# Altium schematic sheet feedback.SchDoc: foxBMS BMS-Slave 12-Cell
size A3; DocumentNumber: 6; SheetNumber: 6; SheetTotal: 15; AUTHOR: Fraunhofer IISB foxBMS Team; SheetDescription: Passive Balancing Feedback
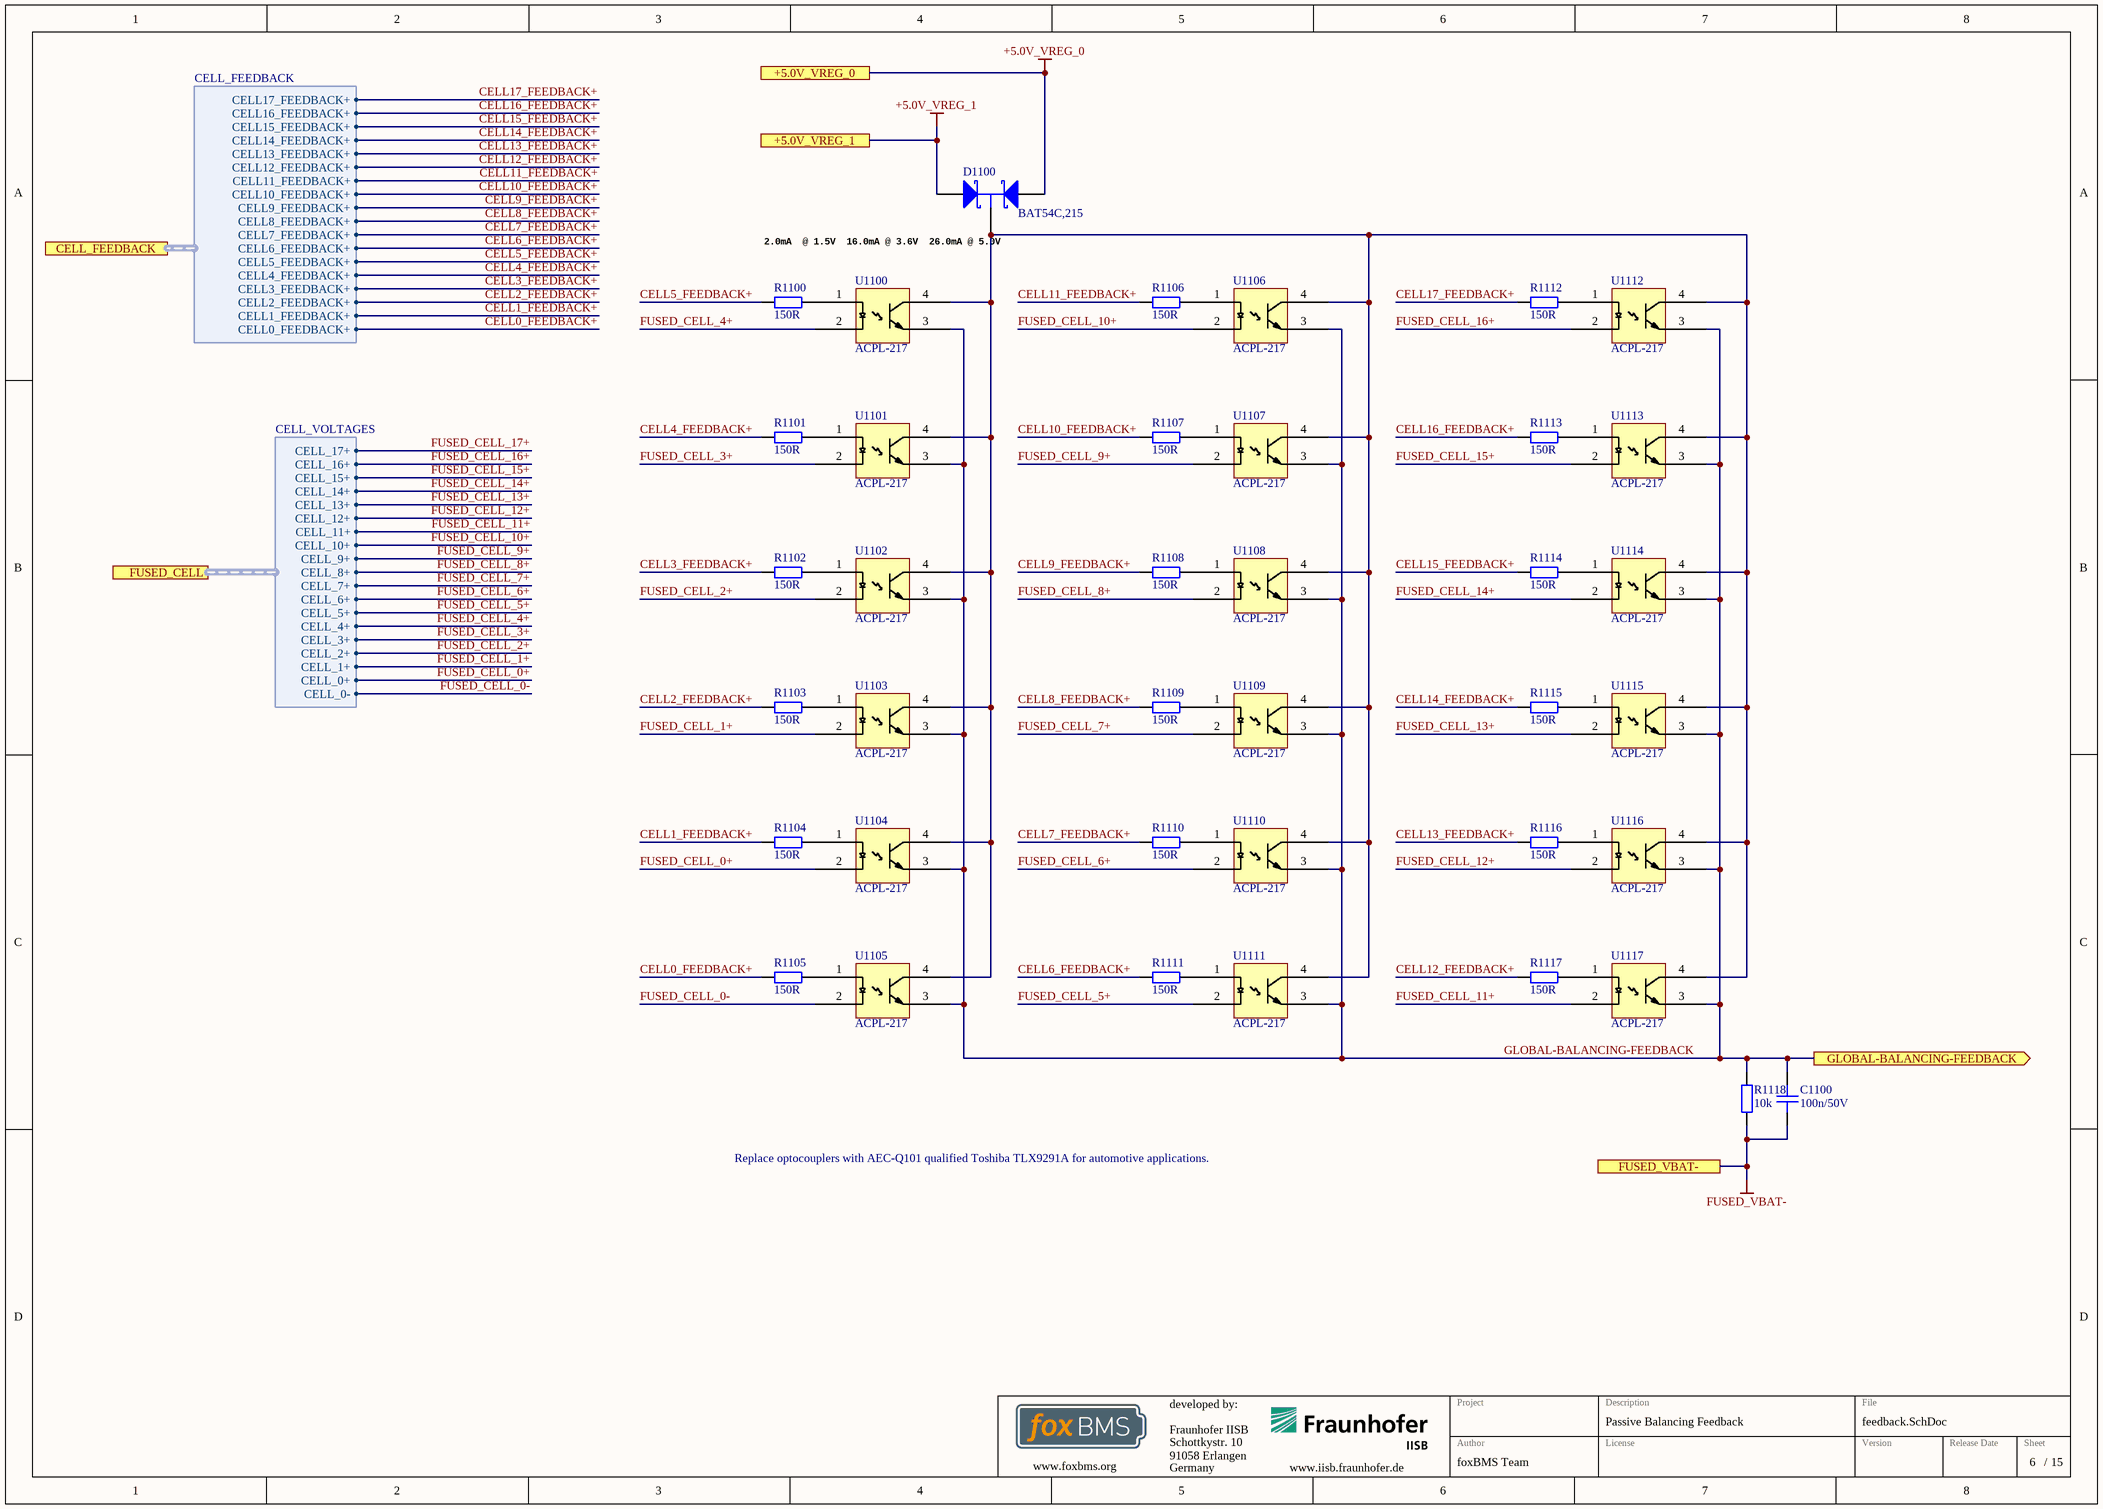
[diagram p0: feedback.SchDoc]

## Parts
C1100  100n/50V  [CAPC1608X08N]
D1100  BAT54C,215  [NXP-SOT23-3_V]
R1100  150R  [RESC1608X05N]
R1101  150R  [RESC1608X05N]
R1102  150R  [RESC1608X05N]
R1103  150R  [RESC1608X05N]
R1104  150R  [RESC1608X05N]
R1105  150R  [RESC1608X05N]
R1106  150R  [RESC1608X05N]
R1107  150R  [RESC1608X05N]
R1108  150R  [RESC1608X05N]
R1109  150R  [RESC1608X05N]
R1110  150R  [RESC1608X05N]
R1111  150R  [RESC1608X05N]
R1112  150R  [RESC1608X05N]
R1113  150R  [RESC1608X05N]
R1114  150R  [RESC1608X05N]
R1115  150R  [RESC1608X05N]
R1116  150R  [RESC1608X05N]
R1117  150R  [RESC1608X05N]
R1118  10k  [RESC1608X05N]
U1100  ACPL-217  [SOIC127P700X220-4N]
U1101  ACPL-217  [SOIC127P700X220-4N]
U1102  ACPL-217  [SOIC127P700X220-4N]
U1103  ACPL-217  [SOIC127P700X220-4N]
U1104  ACPL-217  [SOIC127P700X220-4N]
U1105  ACPL-217  [SOIC127P700X220-4N]
U1106  ACPL-217  [SOIC127P700X220-4N]
U1107  ACPL-217  [SOIC127P700X220-4N]
U1108  ACPL-217  [SOIC127P700X220-4N]
U1109  ACPL-217  [SOIC127P700X220-4N]
U1110  ACPL-217  [SOIC127P700X220-4N]
U1111  ACPL-217  [SOIC127P700X220-4N]
U1112  ACPL-217  [SOIC127P700X220-4N]
U1113  ACPL-217  [SOIC127P700X220-4N]
U1114  ACPL-217  [SOIC127P700X220-4N]
U1115  ACPL-217  [SOIC127P700X220-4N]
U1116  ACPL-217  [SOIC127P700X220-4N]
U1117  ACPL-217  [SOIC127P700X220-4N]

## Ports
+5.0V_VREG_0, +5.0V_VREG_1, CELL_FEEDBACK (harness CELL_FEEDBACK), FUSED_CELL (harness CELL_VOLTAGES), FUSED_VBAT-, GLOBAL-BALANCING-FEEDBACK (out)

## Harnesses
CELL_VOLTAGES: CELL_0-, CELL_0+, CELL_1+, CELL_10+, CELL_11+, CELL_12+, CELL_13+, CELL_14+, CELL_15+, CELL_16+, CELL_17+, CELL_2+, CELL_3+, CELL_4+, CELL_5+, CELL_6+, CELL_7+, CELL_8+, CELL_9+
CELL_FEEDBACK: CELL11_FEEDBACK+, CELL10_FEEDBACK+, CELL9_FEEDBACK+, CELL8_FEEDBACK+, CELL7_FEEDBACK+, CELL6_FEEDBACK+, CELL5_FEEDBACK+, CELL4_FEEDBACK+, CELL3_FEEDBACK+, CELL2_FEEDBACK+, CELL1_FEEDBACK+, CELL0_FEEDBACK+, CELL12_FEEDBACK+, CELL13_FEEDBACK+, CELL14_FEEDBACK+, CELL15_FEEDBACK+, CELL16_FEEDBACK+, CELL17_FEEDBACK+

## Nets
+5.0V_VREG_0: D1100.2(A) ; port +5.0V_VREG_0
+5.0V_VREG_1: D1100.1(A) ; port +5.0V_VREG_1
FUSED_VBAT-: C1100.1 R1118.2 ; port FUSED_VBAT-
CELL0_FEEDBACK+: R1105.1 ; port CELL_FEEDBACK.CELL0_FEEDBACK+
CELL1_FEEDBACK+: R1104.1 ; port CELL_FEEDBACK.CELL1_FEEDBACK+
CELL2_FEEDBACK+: R1103.1 ; port CELL_FEEDBACK.CELL2_FEEDBACK+
CELL3_FEEDBACK+: R1102.1 ; port CELL_FEEDBACK.CELL3_FEEDBACK+
CELL4_FEEDBACK+: R1101.1 ; port CELL_FEEDBACK.CELL4_FEEDBACK+
CELL5_FEEDBACK+: R1100.1 ; port CELL_FEEDBACK.CELL5_FEEDBACK+
CELL6_FEEDBACK+: R1111.1 ; port CELL_FEEDBACK.CELL6_FEEDBACK+
CELL7_FEEDBACK+: R1110.1 ; port CELL_FEEDBACK.CELL7_FEEDBACK+
CELL8_FEEDBACK+: R1109.1 ; port CELL_FEEDBACK.CELL8_FEEDBACK+
CELL9_FEEDBACK+: R1108.1 ; port CELL_FEEDBACK.CELL9_FEEDBACK+
CELL10_FEEDBACK+: R1107.1 ; port CELL_FEEDBACK.CELL10_FEEDBACK+
CELL11_FEEDBACK+: R1106.1 ; port CELL_FEEDBACK.CELL11_FEEDBACK+
CELL12_FEEDBACK+: R1117.1 ; port CELL_FEEDBACK.CELL12_FEEDBACK+
CELL13_FEEDBACK+: R1116.1 ; port CELL_FEEDBACK.CELL13_FEEDBACK+
CELL14_FEEDBACK+: R1115.1 ; port CELL_FEEDBACK.CELL14_FEEDBACK+
CELL15_FEEDBACK+: R1114.1 ; port CELL_FEEDBACK.CELL15_FEEDBACK+
CELL16_FEEDBACK+: R1113.1 ; port CELL_FEEDBACK.CELL16_FEEDBACK+
CELL17_FEEDBACK+: R1112.1 ; port CELL_FEEDBACK.CELL17_FEEDBACK+
FUSED_CELL_0+: U1104.2 ; port FUSED_CELL.CELL_0+
FUSED_CELL_0-: U1105.2 ; port FUSED_CELL.CELL_0-
FUSED_CELL_1+: U1103.2 ; port FUSED_CELL.CELL_1+
FUSED_CELL_2+: U1102.2 ; port FUSED_CELL.CELL_2+
FUSED_CELL_3+: U1101.2 ; port FUSED_CELL.CELL_3+
FUSED_CELL_4+: U1100.2 ; port FUSED_CELL.CELL_4+
FUSED_CELL_5+: U1111.2 ; port FUSED_CELL.CELL_5+
FUSED_CELL_6+: U1110.2 ; port FUSED_CELL.CELL_6+
FUSED_CELL_7+: U1109.2 ; port FUSED_CELL.CELL_7+
FUSED_CELL_8+: U1108.2 ; port FUSED_CELL.CELL_8+
FUSED_CELL_9+: U1107.2 ; port FUSED_CELL.CELL_9+
FUSED_CELL_10+: U1106.2 ; port FUSED_CELL.CELL_10+
FUSED_CELL_11+: U1117.2 ; port FUSED_CELL.CELL_11+
FUSED_CELL_12+: U1116.2 ; port FUSED_CELL.CELL_12+
FUSED_CELL_13+: U1115.2 ; port FUSED_CELL.CELL_13+
FUSED_CELL_14+: U1114.2 ; port FUSED_CELL.CELL_14+
FUSED_CELL_15+: U1113.2 ; port FUSED_CELL.CELL_15+
FUSED_CELL_16+: U1112.2 ; port FUSED_CELL.CELL_16+
GLOBAL-BALANCING-FEEDBACK: C1100.2 R1118.1 U1100.3 U1101.3 U1102.3 U1103.3 U1104.3 U1105.3 U1106.3 U1107.3 U1108.3 U1109.3 U1110.3 U1111.3 U1112.3 U1113.3 U1114.3 U1115.3 U1116.3 U1117.3 ; port GLOBAL-BALANCING-FEEDBACK
NetD1100_3: D1100.3(K) U1100.4 U1101.4 U1102.4 U1103.4 U1104.4 U1105.4 U1106.4 U1107.4 U1108.4 U1109.4 U1110.4 U1111.4 U1112.4 U1113.4 U1114.4 U1115.4 U1116.4 U1117.4
NetR1100_2: R1100.2 U1100.1
NetR1101_2: R1101.2 U1101.1
NetR1102_2: R1102.2 U1102.1
NetR1103_2: R1103.2 U1103.1
NetR1104_2: R1104.2 U1104.1
NetR1105_2: R1105.2 U1105.1
NetR1106_2: R1106.2 U1106.1
NetR1107_2: R1107.2 U1107.1
NetR1108_2: R1108.2 U1108.1
NetR1109_2: R1109.2 U1109.1
NetR1110_2: R1110.2 U1110.1
NetR1111_2: R1111.2 U1111.1
NetR1112_2: R1112.2 U1112.1
NetR1113_2: R1113.2 U1113.1
NetR1114_2: R1114.2 U1114.1
NetR1115_2: R1115.2 U1115.1
NetR1116_2: R1116.2 U1116.1
NetR1117_2: R1117.2 U1117.1

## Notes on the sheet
- (near D1100) 2.0mA  @ 1.5V
  16.0mA @ 3.6V
  26.0mA @ 5.0V
- Replace optocouplers with AEC-Q101 qualified Toshiba TLX9291A for automotive applications.

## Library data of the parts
C1100 = gen_C_ceramic_100n_50V_X7R_0603: MLCC; Capacitance: 100n; Rated Voltage: 50V; Dielectric: X7R; Case EIA: 0603; Case Metric: 1608; PnP Package: C_0603_10; PnP Value: 100n/50V/X7R; PnP equipped: x; Automotive Qualified: True
D1100 = CMP-2000-04915-1: Schottky Barrier Diode, 30 V, 3-Pin SOT23, RoHS, Tape and Reel; Manufacturer: NXP Semiconductors; Forward Surge Current Ifsm Max: 600mA; Pin Configuration: 1A1,2A2,3comK; Package Version: Feb-16; Forward Voltage VF Max: 800mV; SMD Marking: L43/*W1; Diode Case Style: SOT-23; Reverse Recovery Time trr Typ: 5ns; Forward Current If(AV): 200mA; Reel Quantity: 3000; SVHC: NoSVHC(19-Dec-2012); No. of Pins: 3; Junction Temperature Tj Max: 125degC; Common Connection: Cathode; Repetitive Reverse Voltage Vrrm Max: 30V
R1100-R1117 = gen_R_150R_0603: SMD Resistor 150R 0603; Tolerance: 1%; Power: 0.1W; Case EIA: 0603; Case Metric: 1608; Maximum Working Voltage: 75V; PnP Package: R_0603; Automotive Qualified: True
R1118 = gen_R_10k_0603: SMD Resistor 10k 0603; Tolerance: 1%; Power: 0.1W; Case EIA: 0603; Case Metric: 1608; Maximum Working Voltage: 75V; PnP Package: R_0603; Automotive Qualified: True
U1100-U1117 = ACPL-217-56BE: Optocoupler, Transistor Output, 1 Channel; Manufacturer: Broadcom Limited; Automotive Qualified: False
